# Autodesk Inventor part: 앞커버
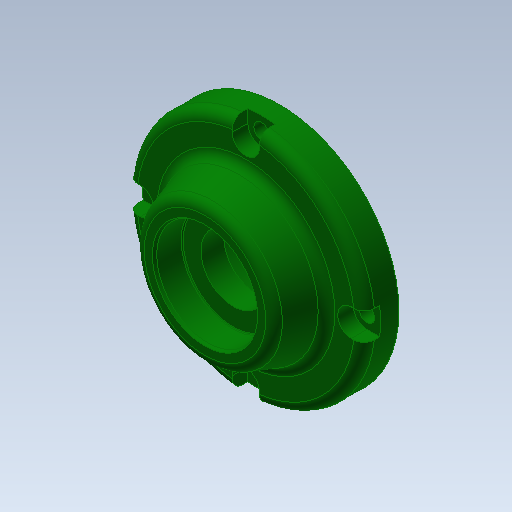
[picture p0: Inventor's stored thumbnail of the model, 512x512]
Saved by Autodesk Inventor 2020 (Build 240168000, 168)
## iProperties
Created: 2017-08
Part Number: 앞커버
Material: 알루미늄 6061
Document SubType Name: Modeling
Designer: mduedu
Density: 1 g/cm^3
Appearance: 진녹색
Author: mduedu
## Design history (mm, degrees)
sketch "스케치1"
  geometry: C1 r 35 at (0, 0); 1 further point
  constraints: 1 centre point, 1 coincident
  dimensions: "d0" = 70 diameter of C1
extrude "돌출1" new body sketch "스케치1" distance "d1" = 10; taper "d2" = 0 deg
sketch "스케치2"
  geometry: C1 r 24 at (0, 0); 1 further point
  constraints: 1 centre point, 1 coincident
  dimensions: "d3" = 48 diameter of C1
node "작업 평면1"
sketch "스케치3"
  geometry: C1 r 20 at (0, 0); 1 further point
  constraints: 1 centre point, 1 coincident
  dimensions: "d5" = 40 diameter of C1
feature "로프트1" sketch "스케치3" dims "d6" = 0, "d7" = 90 deg, "d8" = 0, "d9" = 90 deg
sketch "스케치4"
  geometry: C1 r 24 at (0, 0) reference; 1 further point
extrude "돌출2" join sketch "스케치4" distance "d10" = 8; taper "d11" = 0 deg
hole "구멍1" diameter "d14" = 40; stored, may be unused: countersink angle "d18" = 90 deg, drill point angle "d20" = 0 deg; dims "d12" = 10, "d13" = 10, "d15" = 6, "d16" = 4, "d17" = 2, "d19" = 12
hole "구멍2" diameter "d23" = 34; stored, may be unused: countersink angle "d27" = 90 deg, drill point angle "d29" = 0 deg; dims "d21" = 10, "d22" = 10, "d24" = 6, "d25" = 4, "d26" = 2, "d28" = 3
hole "구멍3" diameter "d32" = 19; stored, may be unused: countersink angle "d36" = 90 deg, drill point angle "d38" = 0 deg; dims "d30" = 10, "d31" = 10, "d33" = 6, "d34" = 4, "d35" = 2, "d37" = 3
chamfer "모따기1" distance "d39" = 1; stored, may be unused: second distance "d40" = 2, angle "d41" = 45 deg
sketch "스케치5"
  geometry: C1 r 15 at (0, 0); 1 further point
  constraints: 1 centre point, 1 coincident
  dimensions: "d42" = 30 diameter of C1
extrude "돌출3" cut sketch "스케치5" distance "d43" = 8.3; taper "d44" = 0 deg
chamfer "모따기2" distance "d47" = 0.8; stored, may be unused: second distance "d48" = 2, angle "d49" = 30 deg
fillet "모깎기1" dims "d50" = 0.3
fillet "모깎기2" dims "d51" = 0.3
fillet "모깎기3" dims "d52" = 3
fillet "모깎기4" dims "d79" = 3
sketch "스케치6" dims "d53" = 58
  geometry: 6 further points
  constraints: 2 vertical alignment, 1 coincident, 7 other
  dimensions: "d56" = 360 deg dimension on point (0, 0) point (0, 29) (derived)
sketch "스케치9" dims "d93" = 62
  geometry: C1 r 35 at (0, 0) reference; 3 further points
  constraints: 2 vertical alignment, 1 coincident, 2 other
hole "구멍6" sketch "스케치9" at (0, 31) diameter "d72" = 4.5; stored, may be unused: countersink angle "d76" = 90 deg, drill point angle "d78" = 0 deg; dims "d73" = 6, "d74" = 8, "d75" = 4.6, "d77" = 8
fillet "모깎기5" dims "d80" = 3
fillet "모깎기6" dims "d81" = 3
sketch "스케치10"
  geometry: L1 (-4, 31)-(4, 31); L2 (4, 31)-(4, 38); L3 (4, 38)-(-4, 38); L4 (-4, 38)-(-4, 31); 6 further points
  constraints: 8 end point, 2 parallel, 1 horizontal, 1 midpoint, 1 perpendicular, 4 other
  dimensions: "d98" = 7 distance of L1.end L2.end
extrude "돌출4" cut sketch "스케치10" stored distance "d88" = 10; taper "d89" = 0 deg
node "솔리드1"
pattern_circular "원형 패턴2" dims angle "d96" = 360 deg
pattern_circular "원형 패턴1" dims angle "d91" = 360 deg
other parameters: "d4" = 12
